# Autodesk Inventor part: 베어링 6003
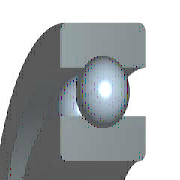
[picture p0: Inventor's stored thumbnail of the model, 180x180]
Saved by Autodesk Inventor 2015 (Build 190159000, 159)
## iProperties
Created: 2012-02
Part Number: 베어링 6003
Material: 강철, 연강
Description: 깊은 그루브 볼 베어링
Document SubType Name: Modeling
Standard: KS B 2023
Designer: mduedu
Standards Organization: KS
Language: ko-KR
Size Designation: 6003 - 17 x 35 x 10
Categories: <MemberInstance><Categories><Category DisplayName="샤프트 부품" InternalName="7f7aeb1f-a693-4053-b835-cee3144e0d98" Mnemonic="SHFT"><Category DisplayName="베어링" Inter
Density: 7.86 g/cm^3
Appearance: 노란색
Mass: 39.0276 g
Surface Area: 48.7538 cm^2
Volume: 4.96535 cm^3
IsCustomPart: 1
Author: mduedu
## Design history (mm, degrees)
sketch "스케치" dims "d0" = 4.68 (= -0.26 x WD + 0.26 x BD)
  geometry: L1 (2.66, 13)-(7.34, 13); L2 (5, 13)-(5, 10.66); L3 (5, 13)-(5, 15.34); L4 (3.261, 11.434)-(0, 11.434); L5 (0, 8.5)-(10, 8.5); L6 (3.261, 14.566)-(0, 14.566); L7 (0, 17.5)-(10, 17.5); L8 (10, 8.5)-(10, 11.434); L9 (6.739, 11.434)-(10, 11.434); L10 (6.739, 14.566)-(10, 14.566); L11 (10, 17.5)-(10, 14.566); L12 (-1.4, 0)-(8.4, 0) reference; L13 (0, -0.3)-(0, 5.3) reference
  constraints: 22 end point, 4 point on line, 2 collinear, 2 perpendicular, 2 symmetric about line, 1 midpoint, 1 parallel, 14 other
  dimensions: "d9" = 17 diameter of L5 L12 (= WD); "d11" = 35 diameter of L7 L12 (= BD); "d12" = 10 distance between parallel lines of L8 L13 (= KB); "d13" = 22.868 diameter of L9 L12 (= 0.326 x BD + 0.674 x WD)
revolve "본체" stored, may be unused: angle "d6" = 90 deg
revolve "볼" stored, may be unused: angle "d7" = 90 deg
pattern_circular "IDS_ARRAYBALL[SIMPL:T]" dims angle "d3" = 360 deg
body "Solid1"
fillet "모깎기1" dims "d1" = 0.3 (= KRS)
other parameters: "WD" = 17 [user parameter; used in 5 equation terms], "BD" = 35 [user parameter; used in 5 equation terms], "KB" = 10 [user parameter; used in 1 equation term], "KRS" = 0.3 [user parameter; used in 1 equation term], "d4" = 0, "d5" = 0, "d8" = 0, "d14" = 0, "d15" = 0, "BBA" = 0 [user parameter], "BC0" = 3250000 [user parameter], "BC" = 6050000 [user parameter], "BR" = 17.5 (= 0.5 x BD) [user parameter], "WR" = 8.5 (= 0.5 x WD) [user parameter]
